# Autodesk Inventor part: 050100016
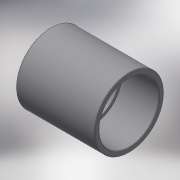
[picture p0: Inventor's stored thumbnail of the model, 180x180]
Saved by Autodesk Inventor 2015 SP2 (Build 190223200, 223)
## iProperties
Created: 2017-10
Part Number: 050100016
Material: Generic
Description: PLASSON SOCKET PVC 16 - CEMENT
Document SubType Name: Modeling
Designer: KIM
Density: 1 g/cm^3
Appearance: Default
Author: KIM
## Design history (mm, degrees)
derived "050100.ipt"
feature "Solid1::050100.ipt"
tag "TaggingFeature1"
body "Solid1"
other parameters: "d1" = 21, "d2" = 14, "d3" = 2, "d4" = 16, "d5" = 14.4, "d7" = 0.16, "d_" = 16, "E_" = 21, "l_" = 14, "Z_" = 2
